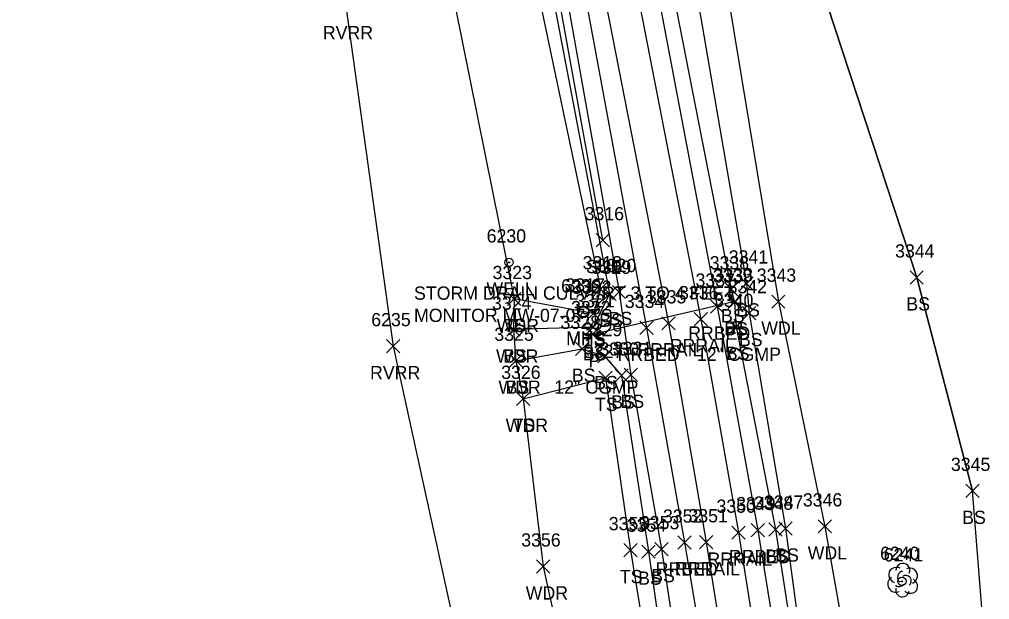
# Model space of a CAD drawing. Extents: x 1462668 to 1465147, y 550359 to 557351.
# Drawn here: x 1464839.5 to 1464986, y 551836.1 to 551923.8 of the extents above; entities that cross this region are included whole.
import ezdxf

# ---------------------------------------------------------------- set-up
doc = ezdxf.new("R2010")
doc.units = 0
for name, color, linetype in [('C_I', 7, 'Continuous'), ('CBP', 7, 'Continuous'), ('D_A', 7, 'Continuous'), ('D_C', 7, 'Continuous'), ('D_I', 7, 'Continuous'), ('D_TIC', 7, 'Continuous'), ('DCP', 7, 'Continuous'), ('L_A', 7, 'Continuous'), ('L_I', 7, 'Continuous'), ('L_TIC', 7, 'Continuous'), ('LAWA', 7, 'Continuous'), ('LAWE', 7, 'Continuous'), ('LELB', 7, 'Continuous'), ('Level 6', 7, 'Continuous'), ('LTD', 7, 'Continuous'), ('R_A', 7, 'Continuous'), ('R_I', 7, 'Continuous'), ('R_TIC', 7, 'Continuous'), ('RR', 7, 'Continuous'), ('RRB', 7, 'Continuous'), ('U_A', 7, 'Continuous'), ('U_C', 7, 'Continuous'), ('U_I', 7, 'Continuous'), ('U_TIC', 7, 'Continuous'), ('USMH', 7, 'Continuous'), ('UUU', 7, 'Continuous'), ('UWW', 7, 'Continuous')]:
    doc.layers.add(name, color=color, linetype=linetype)

msp = doc.modelspace()

# ---------------------------------------------------------------- linework, layer by layer
at = {"layer": 'CBP'}
for radius in [0.625, 0.0833]:
    msp.add_circle((1464972.75, 551838.87), radius, dxfattribs=at)
at = {"layer": 'D_TIC'}
for points in [[(1464946.59, 551880.17), (1464948.59, 551882.17)], [(1464948.59, 551880.17), (1464946.59, 551882.17)], [(1464925.06, 551875.22), (1464927.06, 551877.22)], [(1464927.06, 551875.22), (1464925.06, 551877.22)]]:
    msp.add_lwpolyline(points, dxfattribs=at)
at = {"layer": 'DCP'}
msp.add_lwpolyline([(1464926.06, 551876.22), (1464947.59, 551881.17)], dxfattribs=at)
at = {"layer": 'L_TIC'}
for points in [[(1464948.3, 551882.87), (1464950.3, 551884.87)], [(1464950.3, 551882.87), (1464948.3, 551884.87)], [(1464973.99, 551883.78), (1464975.99, 551885.78)], [(1464975.99, 551883.78), (1464973.99, 551885.78)], [(1464926.24, 551882), (1464928.24, 551884)], [(1464928.24, 551882), (1464926.24, 551884)], [(1464929.04, 551881.58), (1464931.04, 551883.58)], [(1464931.04, 551881.58), (1464929.04, 551883.58)], [(1464946, 551881.99), (1464948, 551883.99)], [(1464948, 551881.99), (1464946, 551883.99)], [(1464913.21, 551880.52), (1464915.21, 551882.52)], [(1464915.21, 551880.52), (1464913.21, 551882.52)], [(1464913.21, 551880.52), (1464915.21, 551882.52)], [(1464915.21, 551880.52), (1464913.21, 551882.52)], [(1464927.62, 551881.31), (1464929.62, 551883.31)], [(1464929.62, 551881.31), (1464927.62, 551883.31)], [(1464946.49, 551880.01), (1464948.49, 551882.01)], [(1464948.49, 551880.01), (1464946.49, 551882.01)], [(1464953.1, 551880.12), (1464955.1, 551882.12)], [(1464955.1, 551880.12), (1464953.1, 551882.12)], [(1464925.2, 551878.31), (1464927.2, 551880.31)], [(1464927.2, 551878.31), (1464925.2, 551880.31)], [(1464948.7, 551878.39), (1464950.7, 551880.39)], [(1464950.7, 551878.39), (1464948.7, 551880.39)], [(1464913.12, 551875.9), (1464915.12, 551877.9)], [(1464915.12, 551875.9), (1464913.12, 551877.9)], [(1464913.12, 551875.9), (1464915.12, 551877.9)], [(1464915.12, 551875.9), (1464913.12, 551877.9)], [(1464925.15, 551876.25), (1464927.15, 551878.25)], [(1464927.15, 551876.25), (1464925.15, 551878.25)], [(1464946.73, 551876.32), (1464948.73, 551878.32)], [(1464948.73, 551876.32), (1464946.73, 551878.32)], [(1464894.94, 551873.4), (1464896.94, 551875.4)], [(1464896.94, 551873.4), (1464894.94, 551875.4)], [(1464923.48, 551873), (1464925.48, 551875)], [(1464925.48, 551873), (1464923.48, 551875)], [(1464913.48, 551871.2), (1464915.48, 551873.2)], [(1464915.48, 551871.2), (1464913.48, 551873.2)], [(1464913.48, 551871.2), (1464915.48, 551873.2)], [(1464915.48, 551871.2), (1464913.48, 551873.2)], [(1464926.85, 551871.89), (1464928.85, 551873.89)], [(1464928.85, 551871.89), (1464926.85, 551873.89)], [(1464927, 551868.6), (1464929, 551870.6)], [(1464929, 551868.6), (1464927, 551870.6)], [(1464929.43, 551868.97), (1464931.43, 551870.97)], [(1464931.43, 551868.97), (1464929.43, 551870.97)], [(1464930.82, 551869.06), (1464932.82, 551871.06)], [(1464932.82, 551869.06), (1464930.82, 551871.06)], [(1464914.57, 551865.45), (1464916.57, 551867.45)], [(1464916.57, 551865.45), (1464914.57, 551867.45)], [(1464914.57, 551865.45), (1464916.57, 551867.45)], [(1464916.57, 551865.45), (1464914.57, 551867.45)], [(1464982.42, 551851.54), (1464984.42, 551853.54)], [(1464984.42, 551851.54), (1464982.42, 551853.54)], [(1464952.66, 551845.69), (1464954.66, 551847.69)], [(1464954.66, 551845.69), (1464952.66, 551847.69)], [(1464954.19, 551845.85), (1464956.19, 551847.85)], [(1464956.19, 551845.85), (1464954.19, 551847.85)], [(1464954.19, 551845.85), (1464956.19, 551847.85)], [(1464956.19, 551845.85), (1464954.19, 551847.85)], [(1464960.11, 551846.18), (1464962.11, 551848.18)], [(1464962.11, 551846.18), (1464960.11, 551848.18)], [(1464930.76, 551842.59), (1464932.76, 551844.59)], [(1464932.76, 551842.59), (1464930.76, 551844.59)], [(1464933.48, 551842.36), (1464935.48, 551844.36)], [(1464935.48, 551842.36), (1464933.48, 551844.36)], [(1464935.46, 551842.74), (1464937.46, 551844.74)], [(1464937.46, 551842.74), (1464935.46, 551844.74)], [(1464917.59, 551840.12), (1464919.59, 551842.12)], [(1464919.59, 551840.12), (1464917.59, 551842.12)]]:
    msp.add_lwpolyline(points, dxfattribs=at)
at = {"layer": 'LAWA'}
for points in [[(1464880.61, 552193.03), (1464893.01, 552155), (1464895.87, 552144.61), (1464904.36, 552119.03), (1464918.93, 552076.52), (1464935.53, 552030.72), (1464934.94, 552010.69), (1464934.13, 551999.11), (1464944.1, 551941.78), (1464954.1, 551881.12), (1464961.11, 551847.18), (1464964.89, 551825.8), (1464985.17, 551830.5)], [(1464822.09, 552191.13), (1464831.12, 552181.23), (1464846.09, 552139.32), (1464854.39, 552125.41), (1464854.76, 552118.31), (1464855.52, 552116.35), (1464856.41, 552111.99), (1464857.4, 552108.26), (1464864.21, 552098.99), (1464865.55, 552089.93), (1464875.65, 552064.09), (1464890.35, 552015.74), (1464891.38, 551985.69), (1464904.19, 551931.25), (1464914.21, 551881.52), (1464914.12, 551876.9), (1464914.48, 551872.2), (1464915.57, 551866.45), (1464918.59, 551841.12), (1464926.38, 551805.64), (1464933.4, 551771.25), (1464941.84, 551717.47), (1464938.82, 551676.13)]]:
    msp.add_lwpolyline(points, dxfattribs=at)
at = {"layer": 'LAWE'}
msp.add_lwpolyline([(1464759.61, 552202.79), (1464780.25, 552180.44), (1464803.55, 552143.82), (1464844.87, 552069.94), (1464864.99, 552018.84), (1464877.43, 551966.68), (1464888.8, 551925.75), (1464895.94, 551874.4), (1464909.19, 551813.8), (1464921.74, 551738.63), (1464922.14, 551696.64), (1464920.4, 551669.35), (1464907.69, 551643.72), (1464887.99, 551607.68), (1464886.95, 551593.62), (1464873.85, 551575.88)], dxfattribs=at)
at = {"layer": 'LELB'}
for points in [[(1464857.07, 552242.46), (1464865.2, 552212.96), (1464870.97, 552191.58), (1464885.97, 552152.01), (1464894.04, 552116.37), (1464905.76, 552072.72), (1464920.4, 552024.45), (1464929.49, 551994.43), (1464932.74, 551964.51), (1464936.27, 551937.8), (1464947, 551882.99), (1464947.49, 551881.01), (1464947.73, 551877.32), (1464953.66, 551846.69), (1464959.08, 551811.5), (1464964.3, 551776.72), (1464969.19, 551734.92), (1464970.84, 551722.67), (1464975.54, 551682.83), (1464978.03, 551647.86), (1464981.7, 551599.51)], [(1464841.77, 552238.45), (1464846.31, 552215.69), (1464847.25, 552212.76), (1464849.98, 552207.37), (1464857.98, 552186.5), (1464868.5, 552146.92), (1464872.78, 552131.98), (1464875.54, 552118.94), (1464878.73, 552113.8), (1464883.37, 552094.34), (1464889.29, 552068.33), (1464901.68, 552020.39), (1464908.94, 551990.33), (1464920.83, 551934.47), (1464930.04, 551882.58), (1464931.82, 551870.06), (1464936.46, 551843.74), (1464941.82, 551807.96), (1464946.97, 551773.69), (1464953.53, 551717.46), (1464958.24, 551678.97), (1464961.44, 551645.4), (1464964.55, 551597.85), (1464966.73, 551546.97)], [(1464856.41, 552111.99), (1464869.05, 552115.12), (1464874.45, 552115.02), (1464880.29, 552093.34), (1464887.37, 552067.85), (1464900.43, 552020.06), (1464907.37, 551989.84), (1464918.72, 551934.1), (1464928.62, 551882.31), (1464926.15, 551877.25), (1464914.12, 551876.9)], [(1464857.4, 552108.26), (1464868.05, 552112.15), (1464873.54, 552110.05), (1464873.56, 552106.23), (1464876.53, 552092.15), (1464884.39, 552066.81), (1464898.94, 552020.35), (1464905.26, 551989.54), (1464916.61, 551933.48), (1464927.24, 551883), (1464926.2, 551879.31), (1464914.21, 551881.52)], [(1464934.94, 552010.69), (1464940.83, 552001.6), (1464955.84, 551943.2), (1464974.99, 551884.78), (1464983.42, 551852.54)], [(1464932.74, 551964.51), (1464939.95, 551938.35), (1464949.3, 551883.87), (1464949.7, 551879.39), (1464955.19, 551846.85)], [(1464914.48, 551872.2), (1464924.48, 551874), (1464927.85, 551872.89), (1464930.43, 551869.97), (1464934.48, 551843.36), (1464939.72, 551807.05), (1464944.24, 551773.43), (1464950.9, 551717.06), (1464955.63, 551678.82), (1464959.4, 551645.2), (1464963.28, 551597.57), (1464964.8, 551546.71), (1464966.53, 551494.93), (1464966.79, 551441.94), (1464968.3, 551401.1), (1464965.92, 551353.61), (1464965.07, 551304.3), (1464962.75, 551247.15), (1464961.36, 551188.58), (1464958.42, 551130.64), (1464955.49, 551094.01), (1464952.56, 551073.69)], [(1464915.57, 551866.45), (1464928, 551869.6), (1464931.76, 551843.59), (1464937.77, 551806.86), (1464942.08, 551772.93), (1464948.71, 551717.27), (1464952.49, 551678.71), (1464957.87, 551644.78), (1464961.45, 551597.92), (1464962.6, 551546.27), (1464963.41, 551495.2), (1464964.92, 551442.3), (1464965.1, 551400.3), (1464964.51, 551353.89), (1464960.59, 551305.34), (1464960.83, 551247.81), (1464957.75, 551187.94), (1464956.49, 551130.72), (1464952.88, 551095.49)], [(1464955.19, 551846.85), (1464959.92, 551811.75), (1464965.81, 551776.66), (1464970.76, 551735.2), (1464972.48, 551722.86), (1464976.64, 551683.01), (1464979.33, 551647.92), (1464983.47, 551599.36)]]:
    msp.add_lwpolyline(points, dxfattribs=at)
at = {"layer": 'Level 6'}
for points in [[(1464985.17, 551830.5), (1464983.42, 551852.54), (1464974.99, 551884.78), (1464955.84, 551943.2), (1464940.83, 552001.6), (1464977.84, 552043.53), (1464965.15, 552055.92), (1464930.69, 552117.79), (1464927.46, 552150.18), (1464907.14, 552143.19), (1464905.9, 552147.55), (1464897.28, 552152.3), (1464893.01, 552155), (1464884.88, 552195.8), (1464882.71, 552216.97), (1464872.17, 552241.98), (1464868.42, 552270.27)], [(1464875.65, 552064.09), (1464864.99, 552018.84), (1464891.38, 551985.69), (1464904.19, 551931.25), (1464914.21, 551881.52), (1464914.12, 551876.9), (1464914.48, 551872.2), (1464915.57, 551866.45), (1464918.59, 551841.12), (1464926.38, 551805.64)]]:
    msp.add_lwpolyline(points, dxfattribs=at)
at = {"layer": 'LTD'}
msp.add_line((1464972.85, 551839.11), (1464972.85, 551839.11), dxfattribs=at)
msp.add_line((1464972.85, 551839.11), (1464972.85, 551839.11), dxfattribs=at)
msp.add_arc((1464972.9, 551840.54), 1.05, 335.5272, 180.9563, dxfattribs=at)
for centre, major_axis, ratio, start_param, end_param in [((1464972.06, 551839.78), (1.21, -0.51), 0.895232, 1.570796, 4.712389), ((1464973.89, 551839.69), (-1.14, -0.48), 0.949671, 1.570796, 4.712389), ((1464971.77, 551838.4), (0.58, -1.04), 0.959034, 3.141593, 6.283185), ((1464972.64, 551839.57), (-0.208, -0.792), 0.645439, 3.141593, 6.283185), ((1464973.35, 551838.94), (-0.5, 0.667), 0.989748, 3.141593, 6.283185), ((1464972.39, 551838.36), (-0.625, -0.083), 0.423636, 0, 3.141593), ((1464973.85, 551838.28), (-1.09, 0.79), 0.841452, 1.570796, 4.712389), ((1464972.85, 551837.61), (0.26, 1.06), 0.942809, 1.570796, 4.712389)]:
    msp.add_ellipse(centre, major_axis=major_axis, ratio=ratio, start_param=start_param, end_param=end_param, dxfattribs=at)
at = {"layer": 'R_TIC'}
for points in [[(1464943.85, 551879.38), (1464945.85, 551881.38)], [(1464945.85, 551879.38), (1464943.85, 551881.38)], [(1464941.41, 551877.48), (1464943.41, 551879.48)], [(1464943.41, 551877.48), (1464941.41, 551879.48)], [(1464933.18, 551876.16), (1464935.18, 551878.16)], [(1464935.18, 551876.16), (1464933.18, 551878.16)], [(1464936.52, 551876.85), (1464938.52, 551878.85)], [(1464938.52, 551876.85), (1464936.52, 551878.85)], [(1464947.1, 551845.23), (1464949.1, 551847.23)], [(1464949.1, 551845.23), (1464947.1, 551847.23)], [(1464950, 551845.61), (1464952, 551847.61)], [(1464952, 551845.61), (1464950, 551847.61)], [(1464938.94, 551843.74), (1464940.94, 551845.74)], [(1464940.94, 551843.74), (1464938.94, 551845.74)], [(1464942.21, 551843.78), (1464944.21, 551845.78)], [(1464944.21, 551843.78), (1464942.21, 551845.78)]]:
    msp.add_lwpolyline(points, dxfattribs=at)
at = {"layer": 'RR'}
for points in [[(1464852.02, 552240.97), (1464860.95, 552211.03), (1464867.46, 552189.38), (1464878.56, 552150.33), (1464888.65, 552114.07), (1464899.65, 552071.44), (1464911.67, 552023.25), (1464918.83, 551992.82), (1464930.96, 551937.24), (1464942.41, 551878.48), (1464948.1, 551846.23), (1464953.71, 551810.6), (1464958.79, 551776.33), (1464965.84, 551719.17), (1464969.85, 551681.61), (1464973.05, 551646.9), (1464976.54, 551599.09), (1464979.47, 551547.89)], [(1464847.44, 552239.37), (1464856.38, 552209.51), (1464862.72, 552188.03), (1464873.7, 552148.91), (1464883.83, 552112.83), (1464894.99, 552070.02), (1464906.93, 552022.21), (1464914.04, 551991.6), (1464926.18, 551935.75), (1464937.52, 551877.85), (1464943.21, 551844.78), (1464948.86, 551809.48), (1464953.8, 551775.61), (1464961, 551718.49), (1464964.95, 551680.7), (1464968.01, 551645.82), (1464971.72, 551598.58), (1464974.51, 551547.48)]]:
    msp.add_lwpolyline(points, dxfattribs=at)
at = {"layer": 'RRB'}
for points in [[(1464855.42, 552240.92), (1464863.56, 552211.63), (1464869.45, 552190.9), (1464882.08, 552151.37), (1464891.39, 552115.24), (1464902.98, 552072.31), (1464915.98, 552024.34), (1464921.97, 551993.58), (1464934.02, 551937.54), (1464944.85, 551880.38), (1464951, 551846.61), (1464956.76, 551811.21), (1464961.88, 551776.42), (1464968.85, 551719.75), (1464973.23, 551681.78), (1464976.32, 551647.69), (1464979.27, 551599.53)], [(1464844.83, 552239.1), (1464853.12, 552208.57), (1464859.71, 552187.12), (1464871.12, 552147.96), (1464880.11, 552112.88), (1464891.67, 552069.24), (1464903.45, 552021.23), (1464911.32, 551990.86), (1464923.48, 551935.24), (1464934.18, 551877.16), (1464939.94, 551844.74), (1464945.92, 551808.83), (1464950.76, 551774.65), (1464957.7, 551718.03), (1464961.72, 551680.01), (1464964.73, 551645.56), (1464968.39, 551597.95), (1464970.75, 551547.2)]]:
    msp.add_lwpolyline(points, dxfattribs=at)
at = {"layer": 'U_TIC'}
for points in [[(1464926.6, 551889.41), (1464928.6, 551891.41)], [(1464928.6, 551889.41), (1464926.6, 551891.41)]]:
    msp.add_lwpolyline(points, dxfattribs=at)
at = {"layer": 'USMH'}
for p, q in [((1464924.65, 551879.64), (1464924.65, 551879.64)), ((1464924.66, 551879.51), (1464924.66, 551879.51)), ((1464925.49, 551879.64), (1464925.49, 551879.64)), ((1464925.49, 551879.51), (1464925.49, 551879.51))]:
    msp.add_line(p, q, dxfattribs=at)
for centre in [(1464924.65, 551879.64), (1464924.66, 551879.51)]:
    msp.add_circle(centre, 0.833, dxfattribs=at)
at = {"layer": 'UUU'}
msp.add_lwpolyline([(1464927.6, 551890.41), (1464906.14, 552008.8)], dxfattribs=at)
at = {"layer": 'UWW'}
for radius in [0.625, 0.0833]:
    msp.add_circle((1464913.45, 551887.05), radius, dxfattribs=at)

# ---------------------------------------------------------------- texts
at = {"layer": 'C_I'}
msp.add_text('6241', height=2, dxfattribs=at).set_placement((1464970.01, 551841.87))
at = {"layer": 'D_A'}
for p in [(1464946.97, 551876.17), (1464925.44, 551871.22)]:
    msp.add_text('P', height=2, dxfattribs=at).set_placement(p)
at = {"layer": 'D_C'}
for p in [(1464941.8, 551872.17), (1464920.28, 551867.22)]:
    msp.add_text('12" CGMP', height=2, dxfattribs=at).set_placement(p)
at = {"layer": 'D_I'}
for s, p in [('3333', (1464944.33, 551884.17)), ('3332', (1464922.8, 551879.22))]:
    msp.add_text(s, height=2, dxfattribs=at).set_placement(p)
at = {"layer": 'L_A'}
for s, p in [('RVRR', (1464885.32, 551920.75)), ('BS', (1464947.75, 551878.87)), ('BS', (1464973.43, 551879.78)), ('TS', (1464925.65, 551878)), ('BS', (1464927.06, 551877.31)), ('BS', (1464928.48, 551877.58)), ('BS', (1464945.44, 551877.99)), ('WDR', (1464911.57, 551876.52)), ('TS', (1464912.62, 551876.52)), ('BS', (1464945.93, 551876.01)), ('WDL', (1464951.52, 551876.12)), ('TS', (1464924.6, 551874.31)), ('BS', (1464948.15, 551874.39)), ('WDR', (1464911.48, 551871.9)), ('BS', (1464912.56, 551871.9)), ('BS', (1464924.59, 551872.25)), ('BS', (1464946.17, 551872.32)), ('RVRR', (1464892.45, 551869.4)), ('BS', (1464922.92, 551869)), ('WDR', (1464911.84, 551867.2)), ('BS', (1464912.92, 551867.2)), ('BS', (1464926.29, 551867.89)), ('TS', (1464926.41, 551864.6)), ('BS', (1464928.87, 551864.97)), ('BS', (1464930.26, 551865.06)), ('WDR', (1464912.93, 551861.45)), ('TS', (1464913.98, 551861.45)), ('BS', (1464981.86, 551847.54)), ('BS', (1464953.63, 551841.85)), ('BS', (1464953.63, 551841.85)), ('WDL', (1464958.53, 551842.18)), ('BS', (1464952.1, 551841.69)), ('TS', (1464930.17, 551838.59)), ('BS', (1464932.92, 551838.36)), ('BS', (1464934.9, 551838.74)), ('WDR', (1464915.96, 551836.12))]:
    msp.add_text(s, height=2, dxfattribs=at).set_placement(p)
at = {"layer": 'L_I'}
for s, p in [('3344', (1464971.73, 551887.78)), ('3318', (1464924.55, 551886)), ('3338', (1464943.74, 551885.99)), ('3341', (1464946.61, 551886.87)), ('3323', (1464910.95, 551884.52)), ('3323', (1464910.95, 551884.52)), ('3319', (1464925.92, 551885.31)), ('3320', (1464926.7, 551885.58)), ('3339', (1464944.22, 551884.01)), ('3343', (1464950.84, 551884.12)), ('3322', (1464922.94, 551882.31)), ('3342', (1464946.44, 551882.39)), ('3324', (1464910.86, 551879.9)), ('3324', (1464910.86, 551879.9)), ('3321', (1464923.46, 551880.25)), ('3340', (1464944.38, 551880.32)), ('6235', (1464892.63, 551877.4)), ('3328', (1464921.22, 551877)), ('3329', (1464924.58, 551875.89)), ('3325', (1464911.22, 551875.2)), ('3325', (1464911.22, 551875.2)), ('3327', (1464924.74, 551872.6)), ('3330', (1464927.09, 551872.97)), ('3331', (1464929.12, 551873.06)), ('3326', (1464912.25, 551869.45)), ('3326', (1464912.25, 551869.45)), ('3345', (1464980.16, 551855.54)), ('3348', (1464950.4, 551849.69)), ('3347', (1464951.93, 551849.85)), ('3347', (1464951.93, 551849.85)), ('3346', (1464957.8, 551850.18)), ('3355', (1464928.5, 551846.59)), ('3354', (1464931.22, 551846.36)), ('3353', (1464933.2, 551846.74)), ('3356', (1464915.28, 551844.12)), ('6240', (1464969.46, 551842.11))]:
    msp.add_text(s, height=2, dxfattribs=at).set_placement(p)
at = {"layer": 'R_A'}
for s, p in [('RRBED', (1464940.49, 551875.38)), ('RRRAIL', (1464932.81, 551872.85)), ('RRRAIL', (1464937.7, 551873.48)), ('RRBED', (1464929.83, 551872.16)), ('RRRAIL', (1464943.39, 551841.23)), ('RRBED', (1464946.64, 551841.61)), ('RRBED', (1464935.58, 551839.74)), ('RRRAIL', (1464938.5, 551839.78))]:
    msp.add_text(s, height=2, dxfattribs=at).set_placement(p)
at = {"layer": 'R_I'}
for s, p in [('3337', (1464941.59, 551883.38)), ('3336', (1464939.1, 551881.48)), ('3334', (1464930.92, 551880.16)), ('3335', (1464934.26, 551880.85)), ('3350', (1464944.76, 551849.23)), ('3349', (1464947.73, 551849.61)), ('3352', (1464936.68, 551847.74)), ('3351', (1464940.52, 551847.78))]:
    msp.add_text(s, height=2, dxfattribs=at).set_placement(p)
at = {"layer": 'U_A'}
for s, p in [('SUB', (1464925.07, 551885.41)), ('WELL', (1464910.02, 551882.05)), ('MHS', (1464922.07, 551874.64)), ('MHS', (1464922.07, 551874.51))]:
    msp.add_text(s, height=2, dxfattribs=at).set_placement(p)
at = {"layer": 'U_C'}
for s, p in [('STORM DRAIN CULVERT 3 TO 4 FEET', (1464899.09, 551881.41)), ('MONITOR MW-07-07', (1464899.09, 551878.05))]:
    msp.add_text(s, height=2, dxfattribs=at).set_placement(p)
at = {"layer": 'U_I'}
for s, p in [('3316', (1464924.85, 551893.41)), ('6230', (1464910.06, 551890.05)), ('6236', (1464921.29, 551882.51)), ('3317', (1464921.96, 551882.64))]:
    msp.add_text(s, height=2, dxfattribs=at).set_placement(p)

doc.saveas('drawing.dxf')
